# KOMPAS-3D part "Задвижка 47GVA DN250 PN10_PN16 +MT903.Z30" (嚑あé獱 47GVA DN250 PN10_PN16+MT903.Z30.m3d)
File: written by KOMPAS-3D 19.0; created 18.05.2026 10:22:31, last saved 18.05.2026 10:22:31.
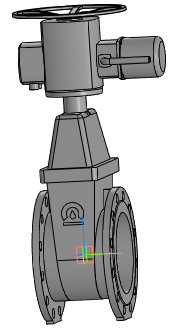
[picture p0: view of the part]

Document properties: Автор: Энергия; Полное имя файла: ..\Задвижка 47GVA DN50_DN1000+MT903.Z\Задвижка 47GVA DN250 PN10_PN16+MT903.Z30.a3d

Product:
- Part/product: Задвижка 47GVA DN250 PN10_PN16 +MT903.Z30
    Масса: 229.696
  - Body: Электропривод MT903.Z20-30
      Масса: 83.2154
  - Body: Задвижка 47GVA DN250 PN10_PN16 без исполнит. мех.
      Масса: 146.481

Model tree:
1. Операция без истории:1
2. Операция без истории:2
